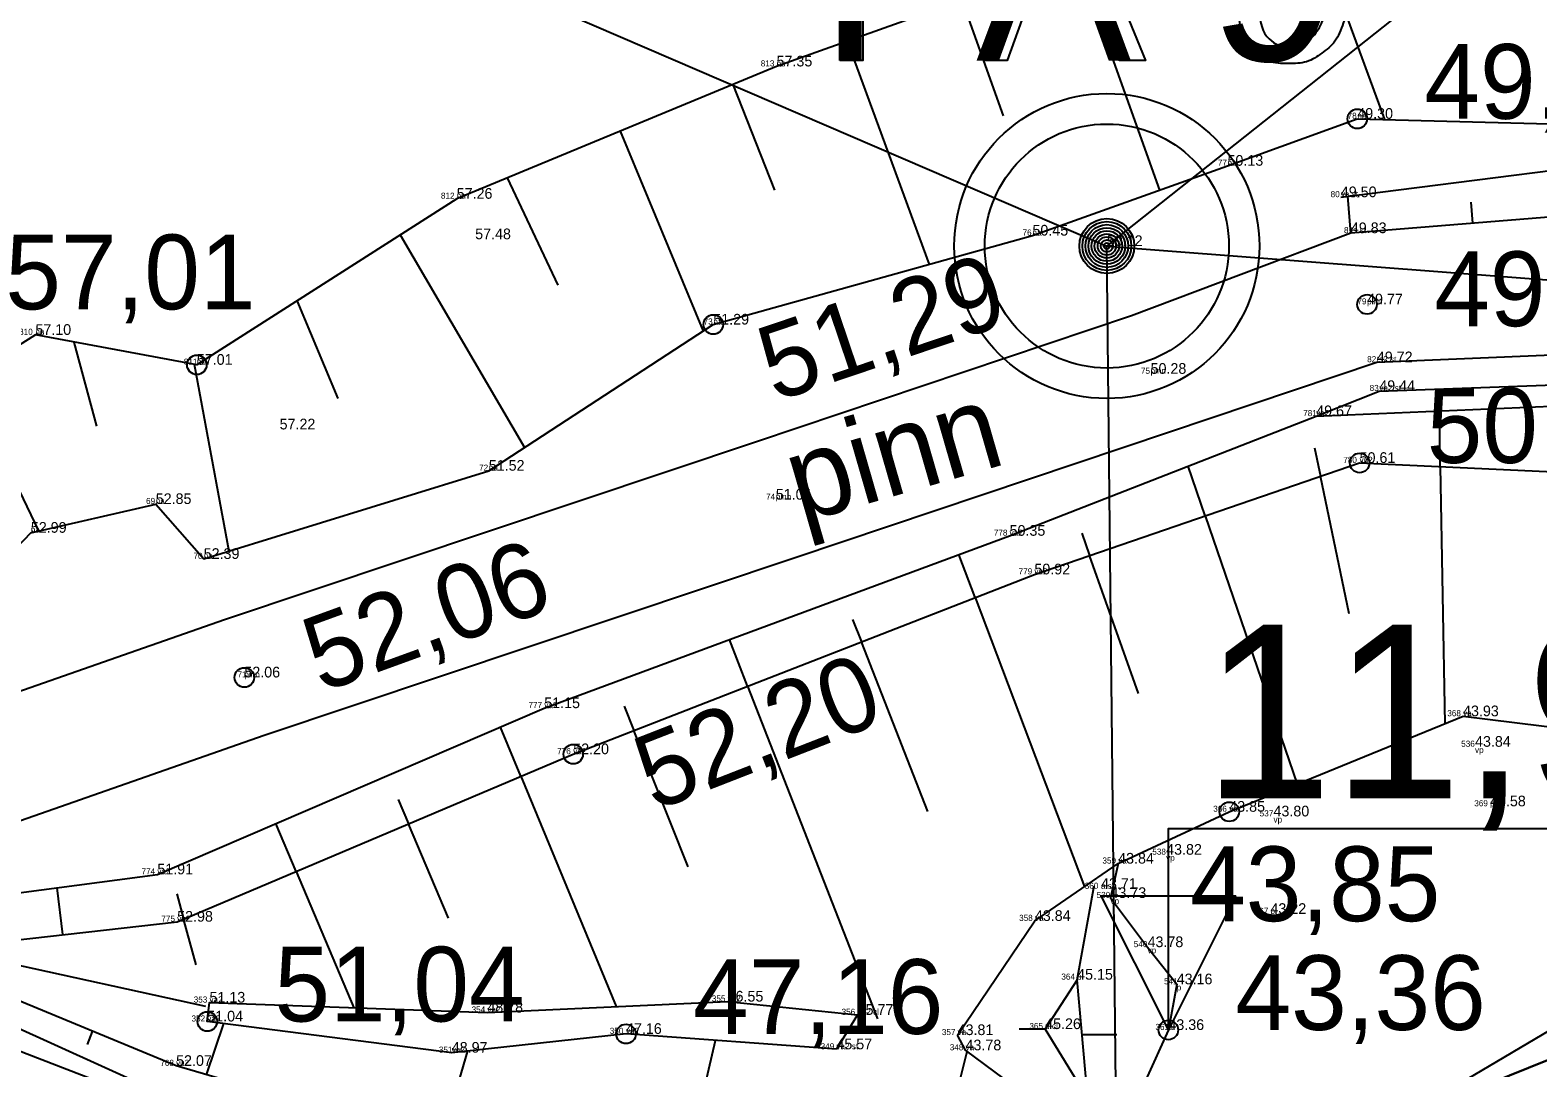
# Model space of a CAD drawing. Extents: x 700746 to 706058, y 6570320 to 6580460.
# Drawn here: x 702898.47 to 702947.88, y 6577382.43 to 6577416.46 of the extents above; entities that cross this region are included whole.
import ezdxf

# ---------------------------------------------------------------- set-up
doc = ezdxf.new("R2010")
doc.units = 0
for name, color, linetype in [('GEOLPUNKT', 7, 'Continuous'), ('jääkpaksus', 7, 'Continuous'), ('KORGUS-EH2000', 7, 'Continuous'), ('Lõige', 7, 'Continuous'), ('MOOTKOOD', 7, 'Continuous'), ('MOOTKORG-EH2000', 7, 'Continuous'), ('MOOTKORG_MUU', 7, 'Continuous'), ('MOOTNR', 7, 'Continuous'), ('RELJEEF', 7, 'Continuous'), ('TEE', 7, 'Continuous'), ('VEEKOGU', 7, 'Continuous')]:
    doc.layers.add(name, color=color, linetype=linetype)

msp = doc.modelspace()

# ---------------------------------------------------------------- linework, layer by layer
at = {"layer": 'GEOLPUNKT'}
msp.add_line((702933.752, 6577409.378), (702933.752, 6577409.378), dxfattribs=at)
for points in [[(702924.998, 6577415.459), (702924.998, 6577421.159), (702927.149, 6577421.159)], [(702929.689, 6577415.459), (702931.88, 6577421.159), (702932.696, 6577421.159), (702935.024, 6577415.459), (702934.165, 6577415.459), (702933.505, 6577417.184), (702931.114, 6577417.184), (702930.489, 6577415.459), (702929.689, 6577415.459)], [(702927.216, 6577417.775), (702925.754, 6577417.775), (702925.754, 6577415.459), (702924.998, 6577415.459)]]:
    msp.add_lwpolyline(points, dxfattribs=at)
for radius in [5, 4, 0.9, 0.801, 0.7, 0.6, 0.5, 0.4, 0.3, 0.2, 0.1]:
    msp.add_circle((702933.752, 6577409.378), radius, dxfattribs=at)
msp.add_open_spline([(702938.77, 6577416.841), (702938.855, 6577416.365), (702939.096, 6577416.151), (702939.337, 6577415.937), (702939.714, 6577415.937), (702940.036, 6577415.937), (702940.28, 6577416.085), (702940.523, 6577416.233), (702940.678, 6577416.48), (702940.832, 6577416.727), (702940.937, 6577417.147), (702941.042, 6577417.567), (702941.042, 6577418.003), (702941.042, 6577418.049), (702941.038, 6577418.143), (702940.828, 6577417.808), (702940.465, 6577417.6), (702940.102, 6577417.392), (702939.678, 6577417.392), (702938.971, 6577417.392), (702938.482, 6577417.905), (702937.992, 6577418.418), (702937.992, 6577419.257), (702937.992, 6577420.124), (702938.503, 6577420.652), (702939.014, 6577421.181), (702939.783, 6577421.181), (702940.339, 6577421.181), (702940.799, 6577420.882), (702941.259, 6577420.582), (702941.498, 6577420.029), (702941.737, 6577419.475), (702941.737, 6577418.426), (702941.737, 6577417.334), (702941.5, 6577416.687), (702941.263, 6577416.04), (702940.795, 6577415.702), (702940.327, 6577415.364), (702939.697, 6577415.364), (702939.029, 6577415.364), (702938.605, 6577415.735), (702938.182, 6577416.107), (702938.096, 6577416.78)], degree=3, dxfattribs=at)
at = {"layer": 'jääkpaksus'}
msp.add_lwpolyline([(702935.77, 6577383.675), (702935.77, 6577390.275), (702957.77, 6577390.275)], dxfattribs=at)
msp.add_lwpolyline([(702935.77, 6577383.675), (702933.57, 6577388.075), (702937.97, 6577388.075)], close=True, dxfattribs=at)
at = {"layer": 'KORGUS-EH2000'}
for centre in [(702941.96, 6577413.549), (702942.281, 6577407.464), (702920.856, 6577406.804), (702903.931, 6577405.484), (702942.035, 6577402.266), (702905.489, 6577395.233), (702916.266, 6577392.717), (702937.765, 6577390.829), (702904.274, 6577383.953), (702917.996, 6577383.546), (702935.77, 6577383.675)]:
    msp.add_circle(centre, 0.32, dxfattribs=at)
at = {"layer": 'Lõige'}
for points in [[(702834.687, 6577213.734), (702849.883, 6577229.558), (702901.645, 6577283.339), (702934.372, 6577351.305), (702933.752, 6577409.378), (702972.502, 6577440.12), (702995.067, 6577474.124)], [(702827.903, 6577444.245), (702862.38, 6577440.12), (702933.752, 6577409.378), (703016.385, 6577403.046), (703082.772, 6577387.952), (703210.312, 6577440.12), (703229.197, 6577449.305)]]:
    msp.add_lwpolyline(points, dxfattribs=at)
at = {"layer": 'RELJEEF'}
for p, q in [((702939.974, 6577421.385), (702942.849, 6577413.526)), ((702932.778, 6577418.779), (702935.478, 6577411.211)), ((702930.361, 6577413.649), (702929.01, 6577417.435)), ((702925.243, 6577416.091), (702927.932, 6577408.777)), ((702922.875, 6577411.213), (702921.503, 6577414.676)), ((702917.807, 6577413.146), (702920.522, 6577406.587)), ((702915.773, 6577408.095), (702914.111, 6577411.616)), ((702941.749, 6577409.8), (702941.651, 6577411.008)), ((702945.679, 6577410.819), (702945.736, 6577410.124)), ((702910.594, 6577409.743), (702914.669, 6577402.774)), ((702908.559, 6577404.378), (702907.224, 6577407.589)), ((702900.657, 6577403.474), (702899.908, 6577406.23)), ((702903.841, 6577405.501), (702904.985, 6577399.376)), ((702896.351, 6577405.012), (702898.742, 6577400.035)), ((702944.681, 6577402.145), (702944.649, 6577403.972)), ((702940.561, 6577402.766), (702940.757, 6577401.828)), ((702936.973, 6577400.53), (702936.414, 6577402.161)), ((702944.681, 6577402.145), (702944.828, 6577393.716)), ((702941.696, 6577397.324), (702940.757, 6577401.828)), ((702936.973, 6577400.53), (702939.988, 6577391.738)), ((702932.929, 6577399.966), (702933.189, 6577399.233)), ((702929.435, 6577397.854), (702928.903, 6577399.261)), ((702934.794, 6577394.712), (702933.189, 6577399.233)), ((702929.435, 6577397.854), (702933.025, 6577388.373)), ((702925.423, 6577397.133), (702925.709, 6577396.401)), ((702921.982, 6577394.947), (702921.386, 6577396.476)), ((702927.881, 6577390.833), (702925.709, 6577396.401)), ((702921.982, 6577394.947), (702926.237, 6577384.039)), ((702917.94, 6577394.287), (702918.256, 6577393.493)), ((702914.549, 6577391.991), (702913.879, 6577393.608)), ((702920.033, 6577389.025), (702918.256, 6577393.493)), ((702914.549, 6577391.991), (702917.677, 6577384.439)), ((702910.529, 6577391.228), (702910.865, 6577390.432)), ((702907.182, 6577388.873), (702906.517, 6577390.444)), ((702912.174, 6577387.34), (702910.865, 6577390.432)), ((702907.182, 6577388.873), (702909.073, 6577384.403)), ((702899.54, 6577386.8), (702899.353, 6577388.34)), ((702903.275, 6577388.135), (702903.498, 6577387.315)), ((702932.779, 6577385.324), (702933.332, 6577388.398)), ((702903.906, 6577385.809), (702903.498, 6577387.315)), ((702904.231, 6577384.439), (702895.566, 6577386.349)), ((702900.346, 6577383.203), (702900.516, 6577383.63)), ((702904.249, 6577382.205), (702904.814, 6577383.884)), ((702931.731, 6577383.704), (702930.881, 6577383.704)), ((702919.663, 6577377.932), (702920.929, 6577383.331)), ((702932.939, 6577383.531), (702934.085, 6577383.531)), ((702911.926, 6577379.957), (702912.808, 6577382.986)), ((702927.451, 6577376.105), (702929.174, 6577382.969))]:
    msp.add_line(p, q, dxfattribs=at)
for points in [[(703081.591, 6577433.914), (703051.255, 6577439.027), (703044.9, 6577437.228), (703028.405, 6577437.067), (703023.926, 6577437.023), (703023.926, 6577437.023), (703022.122, 6577437.006), (703010.161, 6577438.912), (702999.311, 6577434.95), (702985.226, 6577430.27), (702981.377, 6577425.236), (702969.688, 6577426.486), (702959.208, 6577427.828), (702953.454, 6577426.59), (702943.094, 6577422.526), (702935.783, 6577419.852), (702922.929, 6577415.266), (702912.447, 6577410.927), (702903.931, 6577405.484), (702898.641, 6577406.465), (702883.139, 6577396.626), (702867.868, 6577390.782)], [(702937.707, 6577412.01), (702941.96, 6577413.549), (702953.296, 6577413.251), (702964.816, 6577411.894), (702980.059, 6577408.98), (702990.912, 6577407.965), (703006.037, 6577405.117), (703018.41, 6577403.322), (703026.203, 6577402.834), (703036.995, 6577403.54), (703045.22, 6577401.795), (703059.88, 6577400.24), (703065.141, 6577399.485), (703068.887, 6577399.565), (703070.695, 6577396.732)], [(702941.42, 6577410.979), (702953.447, 6577412.511), (702964.949, 6577410.711), (702979.963, 6577407.963), (702991.071, 6577406.266), (703006.265, 6577403.957), (703018.593, 6577401.987), (703024.671, 6577401.281), (703036.778, 6577401.952), (703044.974, 6577401.194), (703051.533, 6577400.105)], [(702854.295, 6577385.64), (702865.911, 6577388.076), (702874.455, 6577389.666), (702886.411, 6577391.958), (702894.626, 6577395.931), (702898.492, 6577399.977), (702902.584, 6577400.919), (702904.156, 6577399.119), (702913.498, 6577402.011), (702920.856, 6577406.804), (702931.315, 6577409.72), (702937.707, 6577412.01)], [(702940.613, 6577403.8), (702942.682, 6577404.624), (702954.166, 6577405.029), (702965.002, 6577403.983), (702978.507, 6577402.115), (702989.781, 6577400.439), (703005.921, 6577398.178), (703009.632, 6577398.02), (703010.426, 6577396.8), (703009.6, 6577394.471), (703007.747, 6577393.069), (703004.595, 6577392.894), (702998.878, 6577392.198), (702996.89, 6577391.956), (702993.099, 6577392.676)], [(702959.276, 6577364.547), (702943.922, 6577369.296), (702928.7, 6577373.581), (702914.965, 6577377.676), (702902.346, 6577381.794), (702893.216, 6577385.926), (702892.965, 6577387.489), (702902.637, 6577388.777), (702915.316, 6577394.226), (702930.566, 6577399.878), (702940.613, 6577403.8), (702954.991, 6577404.413), (702972.228, 6577402.419), (702989.167, 6577399.922), (703001.859, 6577398.018), (703005.921, 6577398.178)], [(702957.946, 6577366.452), (702944.292, 6577370.593), (702930.162, 6577375.469), (702915.527, 6577378.902), (702903.252, 6577382.497), (702894.301, 6577386.205), (702903.286, 6577387.225), (702916.266, 6577392.717), (702931.378, 6577398.612), (702942.035, 6577402.266), (702955.937, 6577401.629), (702970.396, 6577399.697), (702989.632, 6577397.26), (703003.85, 6577395.662), (703007.731, 6577396.131)], [(702928.863, 6577383.507), (702931.395, 6577387.25), (702934.124, 6577389.13), (702937.765, 6577390.829), (702945.426, 6577393.961), (702954.817, 6577392.8)], [(702966.923, 6577388.941), (702966.923, 6577388.941), (702960.979, 6577390.597), (702959.582, 6577388.383), (702956.973, 6577387.241), (702955.296, 6577385.197), (702955.475, 6577384.505), (702951.958, 6577383.127), (702948.983, 6577384.083), (702945.08, 6577381.777), (702942.87, 6577379.229), (702942.658, 6577376.128), (702943.146, 6577375.422), (702948.808, 6577374.265)], [(702934.124, 6577389.13), (702933.872, 6577388.002), (702935.087, 6577386.39), (702936.042, 6577385.172), (702935.77, 6577383.675), (702935.02, 6577382.018), (702934.405, 6577381.869), (702932.628, 6577380.407)], [(702933.128, 6577381.415), (702932.779, 6577385.324), (702931.731, 6577383.704), (702933.128, 6577381.415)], [(702924.891, 6577383.041), (702917.996, 6577383.546), (702912.286, 6577382.93), (702904.274, 6577383.953), (702904.346, 6577384.572), (702913.452, 6577384.246), (702921.325, 6577384.606), (702925.586, 6577384.171), (702924.891, 6577383.041)], [(702959.276, 6577364.547), (702960.399, 6577366.521), (702959.509, 6577368.33), (702955.947, 6577370.387), (702953.275, 6577371.416), (702947.147, 6577373.514), (702943.146, 6577375.422), (702940.001, 6577378.521), (702936.785, 6577379.412), (702932.628, 6577380.407), (702929.122, 6577383.008), (702928.863, 6577383.507)]]:
    msp.add_lwpolyline(points, dxfattribs=at)
at = {"layer": 'TEE'}
for points in [[(703066.989, 6577392.569), (703060.3, 6577394.234), (703043.424, 6577397.545), (703036.237, 6577398.538), (703024.237, 6577400.258), (703018.395, 6577401.277), (703005.998, 6577403.09), (702990.891, 6577405.529), (702979.71, 6577407.326), (702964.872, 6577409.776), (702953.234, 6577410.733), (702941.749, 6577409.8), (702934.562, 6577407.088), (702922.267, 6577402.959), (702904.842, 6577397.125), (702895.151, 6577393.739), (702886.815, 6577391.052), (702876.831, 6577388.099), (702854.295, 6577385.64)], [(702892.425, 6577388.657), (702896.425, 6577389.947), (702906.136, 6577393.341), (702923.539, 6577399.167), (702935.81, 6577403.288), (702942.6, 6577405.567), (702953.835, 6577406.041), (702964.855, 6577405.405), (702978.533, 6577402.999), (702989.845, 6577401.545), (703006.737, 6577398.863), (703012.423, 6577398.158), (703046.095, 6577392.829), (703059.287, 6577390.305), (703059.287, 6577390.305)], [(702892.321, 6577388.624), (702892.288, 6577385.241), (702902.125, 6577381.434), (702914.602, 6577377.189), (702928.482, 6577373.225), (702943.935, 6577368.799), (702959.049, 6577364.41), (702963.274, 6577363.624), (702966.639, 6577362.72)]]:
    msp.add_lwpolyline(points, dxfattribs=at)
at = {"layer": 'VEEKOGU'}
for points in [[(702951.004, 6577374.529), (702946.832, 6577375.52), (702943.246, 6577376.387), (702943.548, 6577378.82), (702945.651, 6577381.66), (702949.496, 6577383.207)], [(702949.496, 6577383.207), (702945.651, 6577381.66), (702943.548, 6577378.82), (702943.246, 6577376.387), (702946.832, 6577375.52), (702951.004, 6577374.529)]]:
    msp.add_lwpolyline(points, dxfattribs=at)

# ---------------------------------------------------------------- texts
at = {"layer": 'GEOLPUNKT'}
msp.add_text('PA-9', height=5.7, dxfattribs=at).set_placement((702924.385, 6577415.459))
at = {"layer": 'jääkpaksus'}
msp.add_text('11,94', height=5.7, rotation=360, dxfattribs=at).set_placement((702936.908, 6577391.264))
at = {"layer": 'KORGUS-EH2000'}
for s, p in [('49,30', (702944.16, 6577413.549)), ('57,01', (702897.656, 6577407.303)), ('49,77', (702944.481, 6577406.75)), ('50,61', (702944.235, 6577402.266)), ('43,85', (702936.483, 6577387.242)), ('51,04', (702906.474, 6577383.953)), ('43,36', (702937.97, 6577383.675)), ('47,16', (702920.196, 6577383.546))]:
    msp.add_text(s, height=2.45, dxfattribs=at).set_placement(p)
for s, rotation, p in [('51,29', 18.6396, (702922.868, 6577404.26)), ('52,06', 20.0017, (702908.004, 6577394.724)), ('52,20', 21.3217, (702918.916, 6577390.839))]:
    msp.add_text(s, height=2.45, rotation=rotation, dxfattribs=at).set_placement(p)
at = {"layer": 'MOOTKOOD'}
for s, p in [('vp', (702945.818, 6577392.76)), ('vp', (702939.214, 6577390.477)), ('vp', (702935.696, 6577389.221)), ('vp', (702933.872, 6577387.802)), ('vp', (702935.087, 6577386.19)), ('p', (702936.042, 6577384.972))]:
    msp.add_text(s, height=0.2, dxfattribs=at).set_placement(p)
at = {"layer": 'MOOTKORG-EH2000'}
for s, p in [('57.35', (702922.929, 6577415.266)), ('49.30', (702941.96, 6577413.549)), ('49.30', (702941.96, 6577413.549)), ('50.13', (702937.707, 6577412.01)), ('57.26', (702912.447, 6577410.927)), ('49.50', (702941.42, 6577410.979)), ('57.48', (702913.053, 6577409.601)), ('50.45', (702931.315, 6577409.72)), ('49.83', (702941.749, 6577409.8)), ('50.12', (702933.752, 6577409.378)), ('49.77', (702942.281, 6577407.464)), ('57.10', (702898.641, 6577406.465)), ('51.29', (702920.856, 6577406.804)), ('51.29', (702920.856, 6577406.804)), ('57.01', (702903.931, 6577405.484)), ('49.72', (702942.6, 6577405.567)), ('49.72', (702942.6, 6577405.567)), ('50.28', (702935.186, 6577405.188)), ('49.44', (702942.682, 6577404.624)), ('49.67', (702940.613, 6577403.8)), ('57.22', (702906.644, 6577403.365)), ('51.52', (702913.498, 6577402.011)), ('50.61', (702942.035, 6577402.266)), ('51.04', (702922.903, 6577401.063)), ('52.85', (702902.584, 6577400.919)), ('52.99', (702898.492, 6577399.977)), ('50.35', (702930.566, 6577399.878)), ('52.39', (702904.156, 6577399.119)), ('50.92', (702931.378, 6577398.612)), ('52.06', (702905.489, 6577395.233)), ('51.15', (702915.316, 6577394.226)), ('43.93', (702945.426, 6577393.961)), ('52.20', (702916.266, 6577392.717)), ('43.84', (702945.818, 6577392.96)), ('43.85', (702937.765, 6577390.829)), ('43.80', (702939.214, 6577390.677)), ('43.58', (702946.31, 6577391.008)), ('43.82', (702935.696, 6577389.421)), ('51.91', (702902.637, 6577388.777)), ('43.84', (702934.124, 6577389.13)), ('43.71', (702933.562, 6577388.302)), ('43.73', (702933.872, 6577388.002)), ('43.73', (702933.872, 6577388.002)), ('52.98', (702903.286, 6577387.225)), ('43.84', (702931.395, 6577387.25)), ('43.22', (702939.115, 6577387.48)), ('43.78', (702935.087, 6577386.39)), ('45.15', (702932.779, 6577385.324)), ('43.16', (702936.042, 6577385.172)), ('51.13', (702904.346, 6577384.572)), ('48.78', (702913.452, 6577384.246)), ('46.55', (702921.325, 6577384.606)), ('51.04', (702904.274, 6577383.953)), ('45.77', (702925.586, 6577384.171)), ('47.16', (702917.996, 6577383.546)), ('43.81', (702928.863, 6577383.507)), ('45.26', (702931.731, 6577383.704)), ('43.36', (702935.77, 6577383.675)), ('48.97', (702912.286, 6577382.93)), ('45.57', (702924.891, 6577383.041)), ('43.78', (702929.122, 6577383.008)), ('52.07', (702903.252, 6577382.497))]:
    msp.add_text(s, height=0.35, dxfattribs=at).set_placement(p)
at = {"layer": 'MOOTKORG_MUU'}
for s, p in [('nu', (702922.929, 6577415.266)), ('na', (702941.96, 6577413.549)), ('na', (702937.707, 6577412.01)), ('nu', (702912.447, 6577410.927)), ('va st', (702941.42, 6577410.979)), ('na', (702931.315, 6577409.72)), ('ts st', (702941.749, 6577409.8)), ('pinn', (702942.281, 6577407.464)), ('na', (702920.856, 6577406.804)), ('nu', (702898.641, 6577406.465)), ('nu', (702903.931, 6577405.484)), ('pinn', (702935.186, 6577405.188)), ('ts2 st', (702942.6, 6577405.567)), ('va2 st', (702942.682, 6577404.624)), ('va2', (702940.613, 6577403.8)), ('vu2', (702942.035, 6577402.266)), ('na', (702913.498, 6577402.011)), ('na', (702902.584, 6577400.919)), ('pinn', (702922.903, 6577401.063)), ('na', (702898.492, 6577399.977)), ('va2', (702930.566, 6577399.878)), ('na', (702904.156, 6577399.119)), ('vu2', (702931.378, 6577398.612)), ('pinn', (702905.489, 6577395.233)), ('va2', (702915.316, 6577394.226)), ('va', (702945.426, 6577393.961)), ('vu2', (702916.266, 6577392.717)), ('va', (702937.765, 6577390.829)), ('p', (702946.31, 6577391.008)), ('va', (702934.124, 6577389.13)), ('va2', (702902.637, 6577388.777)), ('a st', (702933.562, 6577388.302)), ('p', (702939.115, 6577387.48)), ('vu2', (702903.286, 6577387.225)), ('va', (702931.395, 6577387.25)), ('u', (702932.779, 6577385.324)), ('va2', (702904.346, 6577384.572)), ('va2', (702921.325, 6577384.606)), ('va2', (702904.274, 6577383.953)), ('va2', (702913.452, 6577384.246)), ('va2 cl', (702925.586, 6577384.171)), ('va2', (702917.996, 6577383.546)), ('va', (702928.863, 6577383.507)), ('u cl', (702931.731, 6577383.704)), ('a', (702935.77, 6577383.675)), ('va2', (702912.286, 6577382.93)), ('va2 st', (702924.891, 6577383.041)), ('va', (702929.122, 6577383.008)), ('vu2', (702903.252, 6577382.497))]:
    msp.add_text(s, height=0.2, dxfattribs=at).set_placement(p)
at = {"layer": 'MOOTNR'}
for s, p in [('813', (702922.412, 6577415.266)), ('78', (702941.643, 6577413.549)), ('77', (702937.39, 6577412.01)), ('812', (702911.93, 6577410.927)), ('80', (702941.086, 6577410.979)), ('76', (702930.989, 6577409.72)), ('81', (702941.524, 6577409.8)), ('79', (702941.964, 6577407.464)), ('73', (702920.539, 6577406.804)), ('810', (702898.107, 6577406.465)), ('811', (702903.506, 6577405.484)), ('75', (702934.869, 6577405.188)), ('82', (702942.283, 6577405.567)), ('83', (702942.365, 6577404.624)), ('781', (702940.188, 6577403.8)), ('780', (702941.501, 6577402.266)), ('72', (702913.181, 6577402.011)), ('69', (702902.267, 6577400.919)), ('74', (702922.586, 6577401.063)), ('778', (702930.049, 6577399.878)), ('70', (702903.822, 6577399.119)), ('779', (702930.861, 6577398.612)), ('71', (702905.264, 6577395.233)), ('777', (702914.799, 6577394.226)), ('368', (702944.909, 6577393.961)), ('536', (702945.365, 6577392.96)), ('776', (702915.74, 6577392.717)), ('366', (702937.239, 6577390.829)), ('369', (702945.793, 6577391.008)), ('537', (702938.761, 6577390.677)), ('538', (702935.242, 6577389.421)), ('359', (702933.607, 6577389.13)), ('774', (702902.12, 6577388.777)), ('360', (702933.028, 6577388.302)), ('539', (702933.418, 6577388.002)), ('367', (702938.598, 6577387.48)), ('775', (702902.769, 6577387.225)), ('358', (702930.878, 6577387.25)), ('540', (702934.634, 6577386.39)), ('364', (702932.262, 6577385.324)), ('541', (702935.627, 6577385.172)), ('353', (702903.829, 6577384.572)), ('355', (702920.808, 6577384.606)), ('352', (702903.757, 6577383.953)), ('354', (702912.935, 6577384.246)), ('356', (702925.06, 6577384.171)), ('350', (702917.462, 6577383.546)), ('357', (702928.346, 6577383.507)), ('365', (702931.214, 6577383.704)), ('361', (702935.345, 6577383.675)), ('351', (702911.861, 6577382.93)), ('349', (702924.374, 6577383.041)), ('348', (702928.605, 6577383.008)), ('768', (702902.735, 6577382.497))]:
    msp.add_text(s, height=0.2, dxfattribs=at).set_placement(p)
at = {"layer": 'TEE'}
msp.add_text('pinn', height=2.8, rotation=16.0814, dxfattribs=at).set_placement((702923.713, 6577400.291))

doc.saveas('drawing.dxf')
